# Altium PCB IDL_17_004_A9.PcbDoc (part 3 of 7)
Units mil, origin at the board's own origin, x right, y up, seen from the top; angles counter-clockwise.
Board outline 9493.25 x 7199.68 mil, 6 copper layers (Top Layer - SIG1, Layer 2 - GND1, Layer 3 - PWR1, Layer 4 - PWR2, Layer 5 - GND2, Bottom Layer - SIG2), stack 60.592 mil thick; 403 components, 274 nets, 1834 pads, 1849 vias.
Unrouted connection lines stored in the file: 1.
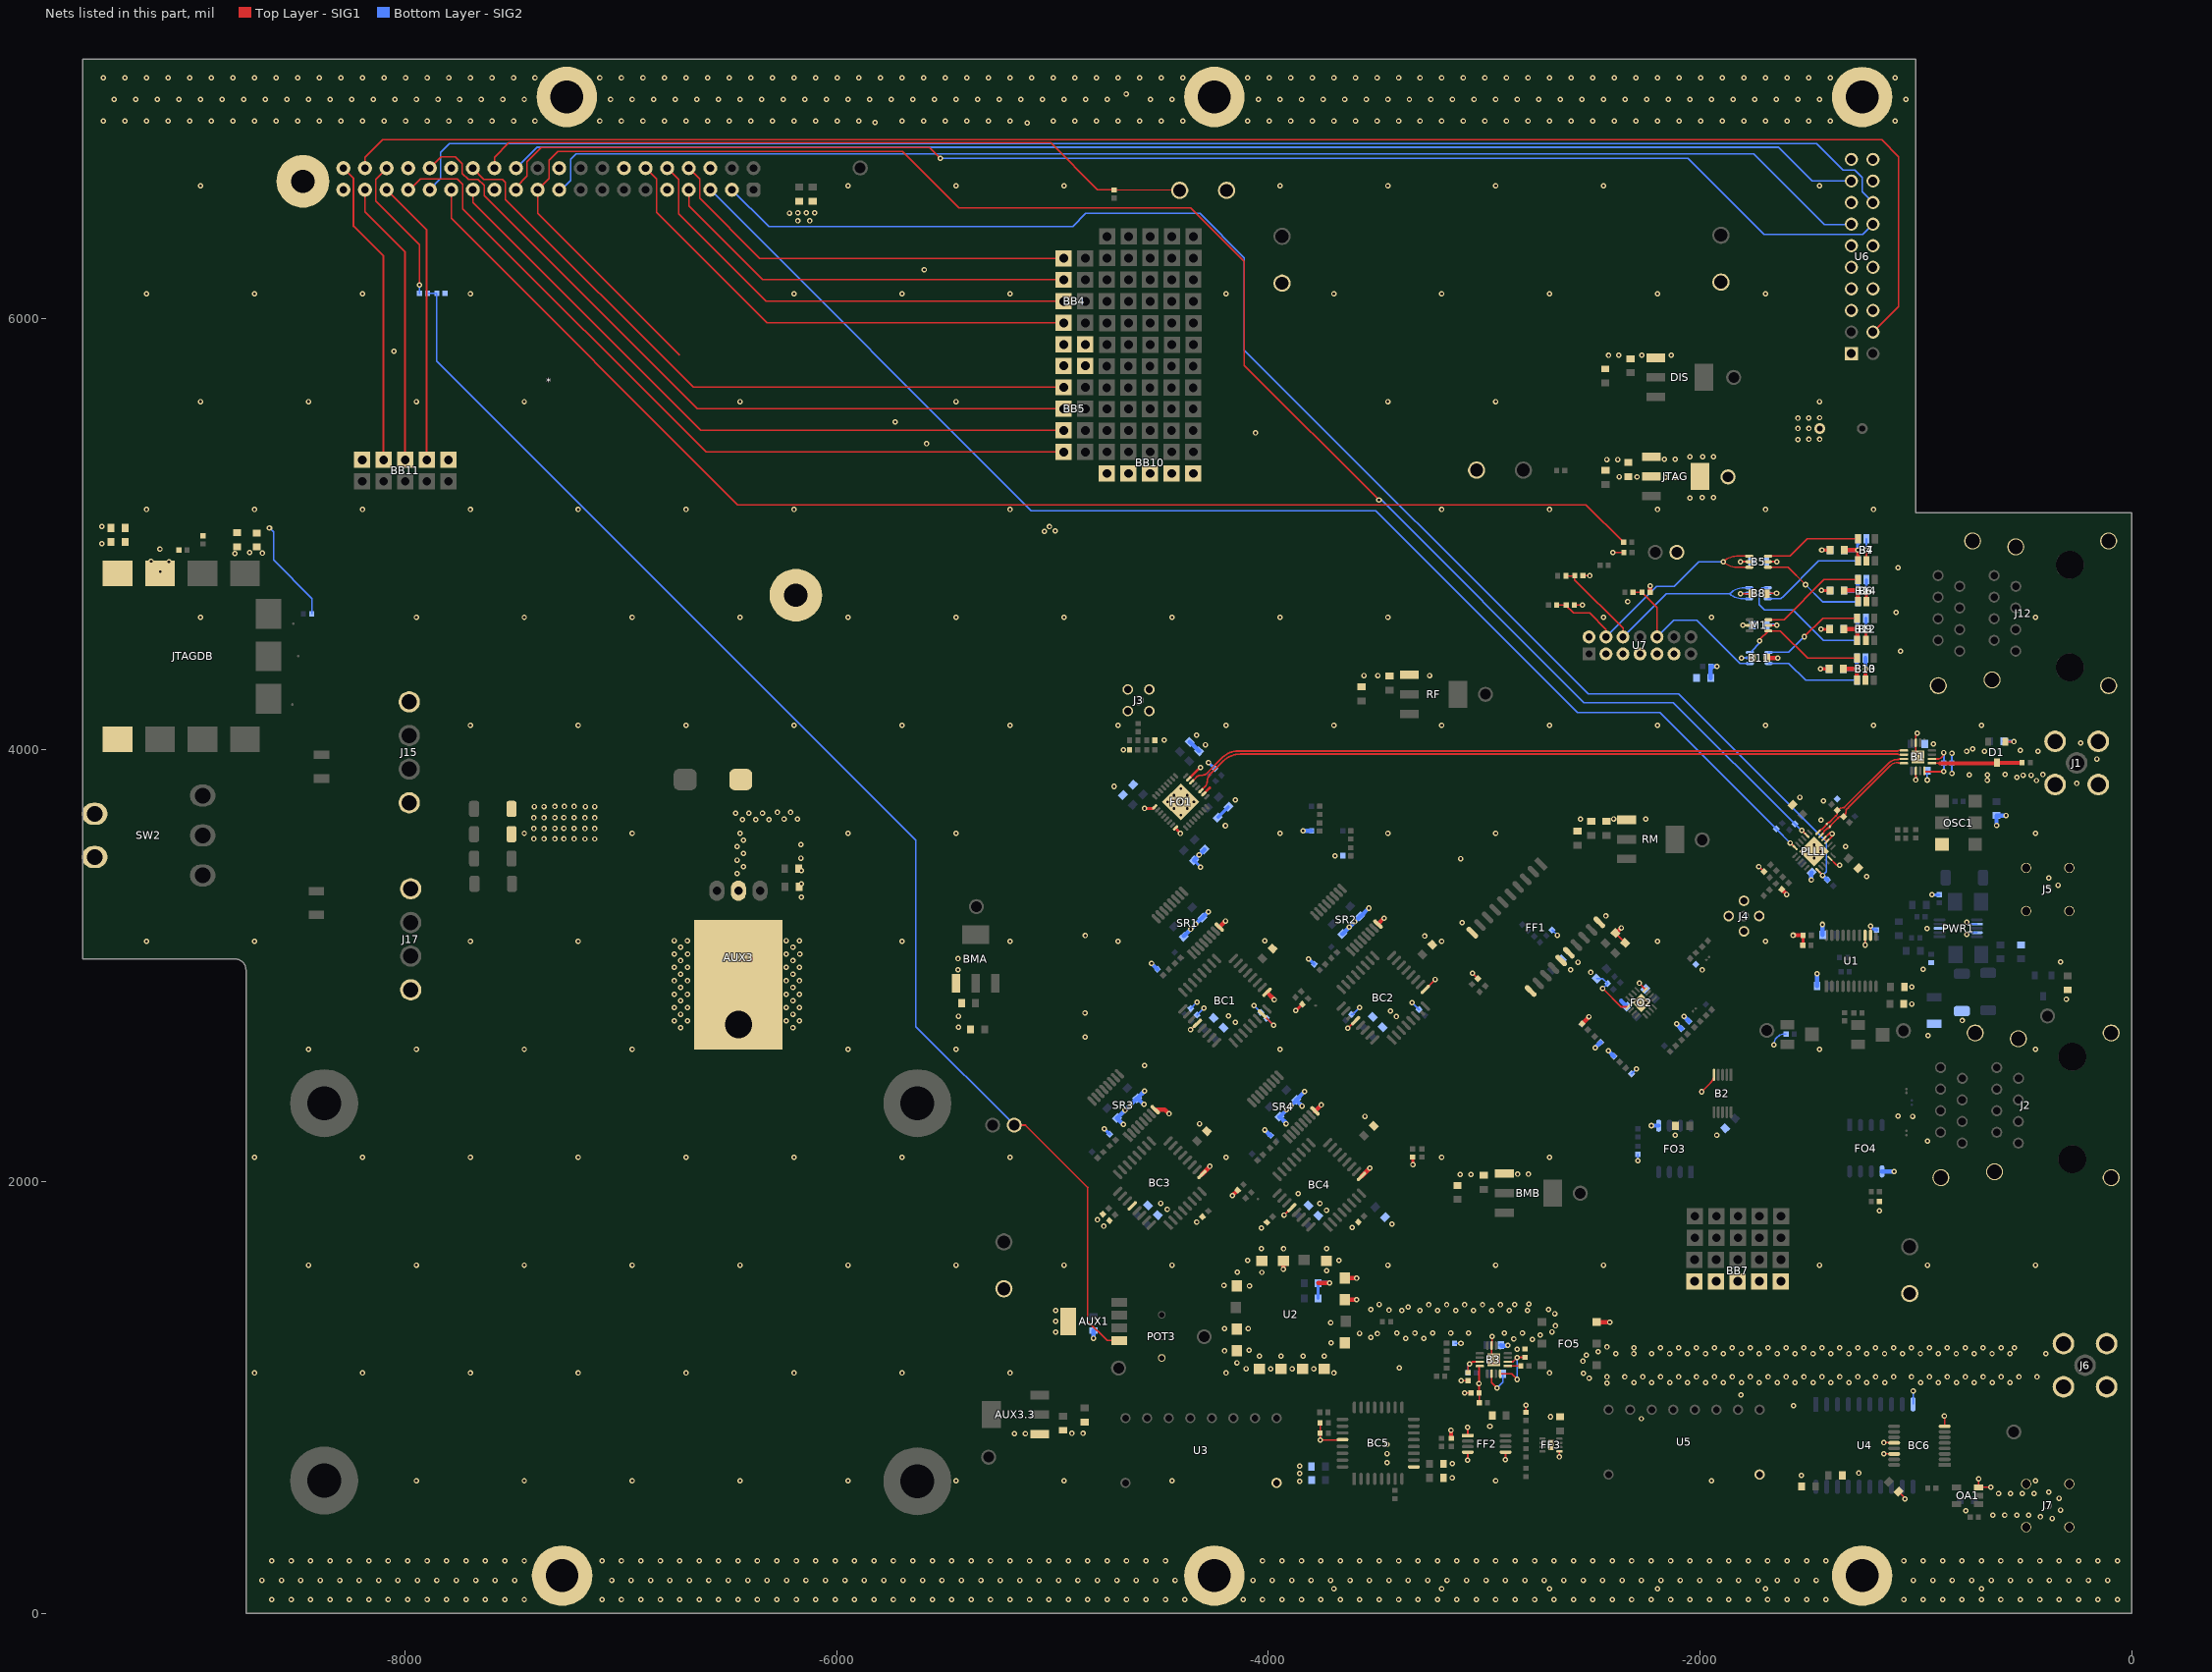
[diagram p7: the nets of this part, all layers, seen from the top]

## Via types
v1: diameter 25, hole 12, Top Layer - SIG1 to Bottom Layer - SIG2, tented both sides, 1502 vias
v2: diameter 25, hole 12, Top Layer - SIG1 to Bottom Layer - SIG2, 184 vias
v3: diameter 25.59, hole 11.81, Top Layer - SIG1 to Bottom Layer - SIG2, tented both sides, 163 vias

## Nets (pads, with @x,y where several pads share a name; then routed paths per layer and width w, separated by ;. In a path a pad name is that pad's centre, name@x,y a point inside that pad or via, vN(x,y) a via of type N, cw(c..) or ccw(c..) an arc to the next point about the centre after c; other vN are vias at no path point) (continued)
GND: *.6 *.9 *.14 *.20 *.25 *.30 *.34 *.39 *.MH2 *.MH3 AUX1.5 AUX3.2 AUX3.3.1 B1.7 B1.14 B1.17 B2.5 B3.7 B3.14 B3.17 B4.2 B5.2 B6.2 B7.2 B8.2 B9.2 B10.2 B11.2 B12.2 B13.2 B14.2 BB4.5 BB4.10 BB5.5 BB5.10 BB7.6 BB7.7 BB7.8 BB7.9 BB7.10 BB10.6 BB10.7 BB10.8 BB10.9 BB10.10 BB11.1 BB11.5 BC1.9 BC1.28 BC2.9 BC2.28 BC3.9 BC3.28 BC4.9 BC4.28 BC5.9 BC5.28 BC6.8 BC6.12 BC6.14 BMA.1 BMB.1 C1.2 C2.1 C3.2 C4.1 C5.2 C6.1 C8.2 C9.1 C11.2 C12.1 C13.2 C14.1 C15.2 C16.1 C17.2 C20.1 C26.2 C27.2 C28.1 C29.1 C32.1 C33.1 C34.2 C35.1 C36.2 C37.1 C38.2 C42.2 C43.1 C46.2 C47.1 C48.2 C49.1 C50.2 C51.1 C52.2 C53.1 C54.2 C55.2 C56.1 C59.2 C60.1 C61.2 C62.1 C63.2 C64.1 C65.2 C66.1 C67.2 C69.2 C70.1 C71.2 C72.1 C73.1 C74.2 C75.1 C76.2 C77.1 C78.2 C79.1 C80.2 C81.1 C84.1 C86.2 C87.2 C88.2 C89.2 C90.1 C91.2 C92.1 C93.2 C94.1 C95.2 C96.1 C97.2 C98.1 C99.2 C100.1 C101.2 C102.1 C103.1 C104.1 C105.1 C106.1 C107.1 C108.1 C109.1 C110.1 C111.1 C112.2 C113.1 C114.1 C115.1 C116.1 C117.2 C118.1 C119.1 C121.1 C123.1 C124.2 C400.2 C401.2 C402.1 C403.1 D1.1 D4.1 D5.2 D7.2 DIS.1 FAN3.2 FAN4.2 FF1.10 FF1.11 FF1.15 FF1.16 FF1.20 FF2.1 FF2.4 FF2.5 FF3.5 FF3.9 FO1.2 FO1.7 FO1.17 FO1.24 FO1.33 FO2.5 FO2.16 FO2.17 FO3.5 FO4.5 FO5.6 J1.2 J1.3 J1.4 J1.5 J2.17 J2.18 J2.19 J2.20 J2.21 J2.22 J3.2 J3.3 J3.4 J3.5 J4.2 J4.3 J4.4 J4.5 J5.2 J5.3 J5.4 J5.5 J6.2 J6.3 J6.4 J6.5 J7.2 J7.3 J7.4 J7.5 J9.2 J10.2 J11.2 J12.17 J12.18 J12.19 J12.20 J12.21 J12.22 J13.2 J15.1 J15.4 J17.1 J17.4 J18.2 JTAG.1 JTAGDB.1 JTAGDB.10 M1.2 MH1.1 MH2.1 MH3.1 MH4.1 MH5.1 MH6.1 OA1.3 OSC1.3 PLL1.3 PLL1.4 PLL1.23 PLL1.25 POT3.3 PWR1.3 PWR1.7 PWR1.9 R5.2 R8.1 R11.1 R12.1 R15.1 R16.1 R17.1 R18.2 R21.2 R22.1 R25.1 R27.1 R30.1 R36.2 R38.1 R40.2 R43.1 R46.2 R51.1 R52.1 R53.1 R54.1 R55.1 R56.1 R61.2 R62.2 R63.2 R64.2 R68.2 R69.2 R70.2 R71.2 R72.1 R73.1 R78.2 R79.2 R80.2 R81.2 R85.2 R86.2 R87.2 R88.2 R91.2 R92.1 R93.1 R96.1 R100.1 R101.2 R102.2 R120.1 R122.2 R123.1 RA2.2 RF.1 RM.1 SR1.8 SR2.8 SR3.8 SR4.8 SW2.4 SW2.5 U1.12 U1.13 U2.1 U2.3 U2.4 U2.5 U2.6 U2.7 U2.8 U2.9 U2.11 U2.12 U2.13 U2.15 U2.16 U3.10 U4.10 U5.10 U6.1 U6.5 U6.6 U6.7 U6.8 U6.9 U6.10 U6.11 U6.12 U6.15 U6.18 U6.19 U6.20 U7.3 U7.5 U7.7 U7.9 U7.11 | length 7139.8
  Top Layer - SIG1 w6: v1(-3927.01,1845.9) BC4.28@-3892.21,1880.03 ; R100.1@-3760.54,881.98 -3760.22,881.67 R96.1@-3760.22,836.07 -3760.33,835.97 v3(-3760.33,804.07) -3657.91,804.07 BC5.28@-3657.1,804.89 ; v1(-3631.72,2710.81) BC2.28@-3596.12,2746.41 ; v3(-3106.71,1078.21) R93.1@-3074.97,1078.21 ccw(c-3073.2,1076.44) R93.1@-3075.7,1076.44 ; R102.2@-2806.26,931.77 v1(-2806.26,965.16) ; C38.2@-2391.95,3151.33 ccw(c-2390.38,3151.34) -2391.49,3150.23 C36.2@-2347.26,3105.99 ; v1@-1727.88,3460.01 R15.1@-1704.43,3436.57 ; v3@-1359.22,3474.27 cw(c-1359.22,3471.86) v3@-1357.51,3473.57 ; v3(-1236.16,3096.68) U1.13@-1236.16,3141.85 ; U1.12@-1210.57,3141.85 v3(-1210.57,3183.56) ; v1(-1149.6,739.06) v1(-1149.6,739.06) BC6.14@-1101.6,739.11 ; v1(-1149.6,791.06) -1103.46,791.06 cw(c-1103.46,788.43) BC6.12@-1101.6,790.29 ; C79.1@-1080.73,564.34 -1050.69,534.31 v3(-1050.69,530.31) ; v1(-868.51,914.82) -867.35,913.65 BC6.8@-867.35,867.06 ; v1@-709.32,623.34 OA1.3@-709.32,584.8 v1@-653.6,584.8
  Top Layer - SIG1 w8: v1(-4361.08,2704.03) ccw(c-4361.08,2710.37) -4356.59,2705.89 -4329.26,2733.22 ccw(c-4329.26,2726.88) BC1.28@-4333.75,2731.36 ; BC5.9@-3326.39,678.9 BC5.9@-3304.45,678.9 ; BC2.9@-3273.18,2891.17 -3273.12,2891.17 v1(-3227.03,2937.26) ; v3(-3090.43,1021.34) -3090.06,1021.71 R92.1@-3061.29,1021.71 ; v3(-3077.21,710.98) ccw(c-3078.25,712.03) -3076.77,712.03 FF2.4@-3076.77,747.3 ; v3(-3077.21,861.98) cw(c-3078.25,860.93) -3076.77,860.93 FF2.1@-3076.77,824.07 ; v3(-3055.07,2966.16) -3054.99,2966.16 R70.2@-3030.28,2941.45 ; B3.14@-2965.93,1110.87 -2965.93,1070.16 v3(-2940.64,1044.87) ; v1(-2964.12,1283) -2964.12,1242.75 B3.7@-2965.96,1240.91 -2965.96,1199.67 ccw(c-2932.36,1199.67) B3.17@-2956.12,1175.91 ; v3(-2902.21,712.98) ccw(c-2903.73,714.5) -2901.58,714.5 FF2.5@-2901.58,747.3 ; v1@-2651.84,725.25 FF3.5@-2651.84,751.14 ; v1(-2600.68,2981.66) v1@-2600.68,2981.79 ; FF1.20@-2467.28,3201.95 ccw(c-2467.28,3212.67) FF1.20@-2459.71,3205.08 ; v1(-2451.23,2895.03) -2366.15,2809.95 FO2.5@-2333.41,2809.95 ; C38.2@-2391.95,3151.33 ccw(c-2391.95,3157.37) C38.2@-2387.68,3153.1 ; v1(-2281.76,2919.47) -2254.07,2891.78 FO2.16@-2254.07,2889.29 ; v3(-1993.23,2417.03) -1950.61,2459.64 ccw(c-1986.26,2495.29) B2.5@-1935.84,2495.29 ; v3(-1812.68,4872.16) B5.2@-1772.31,4872.16 ; v3(-1812.52,4723.75) C101.2@-1759.48,4723.75 ; M1.2@-1684.37,4577.53 v1@-1644.11,4577.53 ; PLL1.23@-1398.39,3497.18 -1367.77,3466.57 v3(-1354.51,3466.57) ; B4.2@-1229.37,4875.08 v1(-1229.37,4926.26) ; B1.14@-1000.84,3903.53 -1000.2,3861.06 v1@-1000.19,3860.34 ; B1.17@-1000.84,3978.93 B1.7@-1000.84,4033.53 -1000.84,4061.91 cw(c-978.33,4061.91) v1(-994.25,4077.83) ; D1.1@-586.63,4038.23 v1(-546,4038.23) ; PLL1.4@-1426.23,3590.44 PLL1.3@-1412.31,3576.52 -1389.51,3598.57 -1389,3599.08 v1(-1389,3612.42) -1391,3612.42 -1397.33,3618.75 -1401.51,3614.57 PLL1.4@-1426.23,3590.44
  Top Layer - SIG1 w12: FO1.7@-4368.92,3866.7 v1@-4316.12,3919.5 ; FO1.2@-4299.32,3797.1 -4272.08,3824.34
  Top Layer - SIG1 w13: v1(-4574.51,3729.07) -4534.39,3729.07 FO1.17@-4527.09,3736.37 ; FO1.24@-4429.65,3638.93 v1(-4408.08,3613.16)
  Top Layer - SIG1 w14: v1@-3872.35,2792.45 R69.2@-3842.71,2822.09 ; R87.2@-3331.32,2113.95 -3330.95,2113.57 v1(-3330.95,2078.57) ; R30.1@-1524.06,3096 -1524.06,3141.69 R25.1@-1523.74,3142 ; v3(-1442,4376) -1441.86,4375.86 C92.1@-1402.48,4375.86 C92.1@-1402.62,4376 ; v3(-1439.68,4560) -1439.54,4559.86 -1400.16,4559.86 C89.2@-1400.3,4560 ; v3(-1437.86,4739) -1437.72,4738.85 -1398.34,4738.85 C96.1@-1398.49,4739 ; v3(-1436.62,4926) C94.1@-1397.71,4926 ; C89.2@-1398.02,4560.14 C89.2@-1397.87,4560 ; C96.1@-1396.2,4739.14 C96.1@-1396.05,4739 ; B12.2@-1233,4507.82 v3(-1233,4559) ; B14.2@-1230,4686.82 v3(-1230,4738)
  Top Layer - SIG1 w20: SR3.8@-4524.49,2334.44 -4480.57,2334.44 v1(-4460.83,2314.7) ; BC3.9@-4308.14,2033.28 -4271.45,2069.96 v1(-4271.45,2071.48) ; SR1.8@-4227.52,3179.45 v1@-4199.08,3207.9 ; v1(-4166.51,1936.61) R86.2@-4143.26,1959.85 ; BC1.9@-4006.33,2877.98 -3984.57,2856.22 cw(c-3985.75,2855.03) -3984.08,2855.03 -3972.57,2843.53 v1(-3972.57,2843.13) ; v1(-3931.15,1594.06) U2.15@-3931.15,1633 ; SR4.8@-3784.53,2327.73 -3782.8,2327.73 v1(-3754.83,2355.7) ; -3769.33,1530.5 v1@-3716.81,1530.5 ; U2.11@-3646.15,1453 v1(-3591.15,1453) ; U2.12@-3646.15,1553 v1(-3591.57,1553) ; BC4.9@-3569.28,2024.79 v1(-3530.55,2063.51) ; SR2.8@-3492.68,3193.47 v1@-3464.7,3221.45 ; R101.2@-3153.58,811.96 v1@-3153.58,846.9 ; R53.1@-2547.58,2730.94 -2514.83,2763.69 v1(-2514.83,2764.67) ; FO5.6@-2479.15,1350 v1(-2419.12,1350) ; C38.2@-2387.68,3153.1 v1(-2364.76,3176.03) ; v3@-1996.3,2418.3 cw(c-1996.3,2413.96) v3(-1993.23,2417.03) ; R16.1@-1621.92,3354.05 v1@-1598.78,3330.91 ; v3(-1569,3142) R25.1@-1523.74,3142 ; B13.2@-1234.4,4323.63 v1(-1234.4,4374.81)
  Bottom Layer - SIG2 w6: C109.1@-4392.02,3135.26 C109.1@-4392.02,3138.21 ; v1@-3634.35,2704.45 cw(c-3625.36,2704.45) v1(-3631.72,2710.81) ; R91.2@-3136.42,1251.39 v3(-3108.12,1251.39) ; v1(-1659.25,2633.83) cw(c-1609.64,2633.83) -1609.64,2683.44 R17.1@-1601.73,2683.44 ; U4.10@-1013.79,968.71 v1(-1013.79,1030.77)
  Bottom Layer - SIG2 w8: R68.2@-4360.54,2803.01 v1@-4330.84,2832.72 ; R61.2@-4330.59,2772.12 -4298.4,2804.31 v3(-4298.4,2804.63) ; v1@-4277.55,3942.21 v1(-4277.22,3942.21) ; v1(-4066.53,2815.37) -4035.64,2784.48 R63.2@-4035.64,2784.14 ; R62.2@-3615.5,2774.94 -3610.03,2774.94 v1(-3578.43,2806.55) ; v1(-3333.93,2829.68) -3333.7,2829.68 R64.2@-3301.82,2797.8 ; v3(-2974.21,866.98) v3@-2974.06,866.83 ; v3(-2940.64,1044.87) -2913.8,1071.72 C76.2@-2913.8,1110.91 ; R27.1@-2682.86,3166.47 R27.1@-2685.86,3166.47 v1@-2661.5,3142.11 ; v1@-2504.79,2967.33 ccw(c-2503.15,2967.33) v1@-2504.31,2966.17 ; C121.1@-2478.96,2940.83 -2451.42,2940.83 R43.1@-2428.35,2917.76 -2451.08,2895.03 v1(-2451.23,2895.03) ; R52.1@-2317.86,2499.67 v1(-2295.09,2522.44) ; v1@-2289,2097 R71.2@-2289,2127.1 ; v3(-1812.68,4872.16) C91.2@-1761.48,4872.16 ; v3(-1812.52,4723.75) cw(c-1807.69,4718.92) -1807.69,4725.75 B8.2@-1772.83,4725.75 ; v1@-1809.29,4426.75 B11.2@-1769.83,4426.75 ; v1@-1389,3609.57 v1(-1389,3612.42) ; v1(-1229.37,4926.26) B7.2@-1229.37,4977.44 ; C9.1@-948.68,3903.53 -948.68,3861.68 v3(-948,3861) ; v1(-834,3891) C20.1@-834,3939 v1(-834,3985) ; v1@-766.11,3193.68 PWR1.7@-717.81,3193.68 ; v1(-765.33,3145.54) -756.55,3154.31 PWR1.9@-717.81,3154.31
  Bottom Layer - SIG2 w14: v1(-4759.93,2245.42) R72.1@-4734.87,2220.36 ; C17.2@-4345.16,3489.45 v1@-4313.59,3457.89 ; v1(-4277.22,3942.21) R8.1@-4249.21,3914.2 ; C15.2@-4234.79,3687.31 C16.1@-4185.29,3736.81 ; v1@-3812.52,3032.46 R56.1@-3787.58,3007.53 ; C69.2@-3769.33,1459.64 C114.1@-3769.33,1530.5 ; C98.1@-1692.68,4578.53 -1644.32,4578.53 v1(-1644.11,4578.73) ; v3(-1436.62,4926) cw(c-1436.62,4923.04) -1434.53,4925.13 -1399.8,4925.13 ccw(c-1399.8,4928.09) C99.2@-1397.71,4926 ; v3(-1233,4559) B9.2@-1233,4610.18 ; v3(-1230,4738) B6.2@-1230,4789.18 ; v3(-1210.57,3183.56) -1200.69,3173.68 ccw(c-1182.65,3191.71) R38.1@-1182.65,3166.2 ; v1(-926.92,3330) ccw(c-925.99,3330.93) -925.99,3329.61 R123.1@-893.25,3329.61 ; C4.1@-593.52,4040 -550.28,4040 cw(c-550.28,4033.95) v1(-546,4038.23) ; v1(-4153.54,3768.56) cw(c-4152.08,3767.1) -4152.08,3769.16 -4152.69,3768.56 v1(-4153.54,3768.56)
  Bottom Layer - SIG2 w20: v1(-4810.85,1275.22) C116.1@-4810.85,1310.9 ; v1(-4672.31,2265.14) C110.1@-4701.35,2294.18 ccw(c-4701.35,2296.59) -4699.64,2294.88 C60.1@-4607.35,2387.18 ; v1@-4579.31,2360.14 -4605.64,2386.47 ccw(c-4607.35,2384.76) C60.1@-4607.35,2387.18 ; v1(-4574.31,2420.14) C60.1@-4607.35,2387.18 ; v1@-4541.08,3010.76 R55.1@-4513.72,2983.4 ; C109.1@-4392.02,3138.21 C49.1@-4306.39,3223.84 -4305.41,3223.84 v1(-4278.83,3250.42) ; C5.2@-4363.97,4037.26 C107.1@-4321.54,3994.83 ; C17.2@-4345.16,3489.45 C6.1@-4295.66,3538.95 ; v3(-4016.55,2239.69) -3991.28,2214.41 R73.1@-3989.79,2214.41 ; v1@-3918.61,2270.68 ccw(c-3916.91,2272.38) -3916.91,2269.97 -3947.23,2300.3 ccw(c-3948.94,2298.59) C62.1@-3948.94,2301 -3947.41,2301 C67.2@-3870.41,2378 ; C67.2@-3870.82,2378 ccw(c-3872.53,2379.71) C67.2@-3870.12,2379.71 ; v1(-3844.08,2350.68) -3869.7,2376.3 cw(c-3868,2378) C67.2@-3870.41,2378 ; v1(-3838.51,3625.09) R18.2@-3800.03,3625.09 ; v1@-3831.15,2418.68 C67.2@-3870.12,2379.71 ; C114.1@-3769.33,1530.5 -3719.22,1530.5 ccw(c-3719.22,1533.92) v1(-3716.81,1531.5) ; C42.2@-3656.79,3148.27 C43.1@-3576.08,3228.98 -3573.82,3228.98 v3(-3535.35,3267.45) ; v1(-3591.57,1553) ccw(c-3591.57,1556.41) v1@-3589.15,1554 ; v1@-3531.55,2062.69 -3530.73,2063.51 v1(-3530.55,2063.51) ; C75.1@-2923.01,1243.57 -2920.18,1240.74 -2893.22,1240.74 v3(-2891.12,1242.83) ; v1@-2486.28,2621.07 R54.1@-2461.89,2645.47 ; v1@-2423.93,2605.95 R51.1@-2399.52,2581.55 ; -2365.39,2837.75 C26.2@-2338.63,2810.99 ; v3(-2225.77,2260) -2225.48,2259.71 FO3.5@-2192.5,2259.71 ; v3(-2109.5,2732.08) -2109.5,2731.74 R46.2@-2086.83,2709.07 ; v1(-2075.5,2766.08) cw(c-2075.5,2764.28) -2074.23,2765.55 R40.2@-2051.98,2743.3 cw(c-2051.98,2745.1) R40.2@-2053.25,2743.83 ; v1(-1484.9,3398.57) -1484.9,3430.15 C14.1@-1482.6,3432.46 ; v3(-1459,2963) -1458.62,2962.62 C37.1@-1458.62,2906.74 ; v3(-1433,3192) -1432.62,3191.62 C35.1@-1432.62,3143.74 ; v1(-1234.4,4374.81) B10.2@-1234.4,4425.99 ; FO4.5@-1157.72,2047.84 -1102.76,2047.84 cw(c-1102.76,2046.36) v3(-1101.72,2047.4) ; v1(-627.25,3650.83) -627.54,3651.12 C3.2@-627.54,3696.72 -582.36,3696.72 v1(-582.25,3696.83) ; C60.1@-4607.35,2387.18 cw(c-4607.35,2384.76) C60.1@-4607.35,2387.18 ; C60.1@-4607.35,2387.18 C60.1@-4607.35,2387.18 ; C67.2@-3870.41,2378 -3868.72,2376.31 cw(c-3865.29,2379.71) C67.2@-3870.12,2379.71
  other v1: -8617,63.9 -8527,63.9 -8437,63.9 -8347,63.9 -8257,63.9 -8167,63.9 -8077,63.9 -7987,63.9 -7897,63.9 -7807,63.9 -7717,63.9 -7627,63.9 -7537,63.9 -7447,63.9 -7087,63.9 -6997,63.9 -6907,63.9 -6817,63.9 -6727,63.9 -6637,63.9 -6547,63.9 -6457,63.9 -6367,63.9 -6277,63.9 -6187,63.9 -6097,63.9 -6007,63.9 -5917,63.9 -5827,63.9 -5737,63.9 -5647,63.9 -5557,63.9 -5467,63.9 -5377,63.9 -5287,63.9 -5197,63.9 -5107,63.9 -5017,63.9 -4927,63.9 -4837,63.9 -4747,63.9 -4657,63.9 -4567,63.9 -4477,63.9 -4387,63.9 -4117,63.9 -4027,63.9 -3937,63.9 -3847,63.9 -3757,63.9 -3667,63.9 -3577,63.9 -3487,63.9 -3397,63.9 -3307,63.9 -3217,63.9 -3127,63.9 -3037,63.9 -2947,63.9 -2857,63.9 -2767,63.9 -2677,63.9 -2587,63.9 -2497,63.9 -2407,63.9 -2317,63.9 -2227,63.9 -2137,63.9 -2047,63.9 -1957,63.9 -1867,63.9 -1777,63.9 -1687,63.9 -1597,63.9 -1507,63.9 -1417,63.9 -1057,63.9 -967,63.9 -877,63.9 -787,63.9 -697,63.9 -607,63.9 -517,63.9 -427,63.9 -337,63.9 -247,63.9 -157,63.9 -67,63.9 -3697,113.9 -3197,113.9 -2697,113.9 -2197,113.9 -1697,113.9 -697,113.9 -8662,153.9 -8572,153.9 -8482,153.9 -8392,153.9 -8302,153.9 -8212,153.9 -8122,153.9 -8032,153.9 -7942,153.9 -7852,153.9 -7762,153.9 -7672,153.9 -7582,153.9 -7492,153.9 -7042,153.9 -6952,153.9 -6862,153.9 -6772,153.9 -6682,153.9 -6592,153.9 -6502,153.9 -6412,153.9 -6322,153.9 -6232,153.9 -6142,153.9 -6052,153.9 -5962,153.9 -5872,153.9 -5782,153.9 -5692,153.9 -5602,153.9 -5512,153.9 -5422,153.9 -5332,153.9 -5242,153.9 -5152,153.9 -5062,153.9 -4972,153.9 -4882,153.9 -4792,153.9 -4702,153.9 -4612,153.9 -4522,153.9 -4432,153.9 -4072,153.9 -3982,153.9 -3892,153.9 -3802,153.9 -3712,153.9 -3622,153.9 -3532,153.9 -3442,153.9 -3352,153.9 -3262,153.9 -3172,153.9 -3082,153.9 -2992,153.9 -2902,153.9 -2812,153.9 -2722,153.9 -2632,153.9 -2542,153.9 -2452,153.9 -2362,153.9 -2272,153.9 -2182,153.9 -2092,153.9 -2002,153.9 -1912,153.9 -1822,153.9 -1732,153.9 -1642,153.9 -1552,153.9 -1462,153.9 -1012,153.9 -922,153.9 -832,153.9 -742,153.9 -652,153.9 -562,153.9 -472,153.9 -382,153.9 -292,153.9 -202,153.9 -112,153.9 -8617,243.9 -8527,243.9 -8437,243.9 -8347,243.9 -8257,243.9 -8167,243.9 -8077,243.9 -7987,243.9 -7897,243.9 -7807,243.9 -7717,243.9 -7627,243.9 -7537,243.9 -7447,243.9 -7087,243.9 -6997,243.9 -6907,243.9 -6817,243.9 -6727,243.9 -6637,243.9 -6547,243.9 -6457,243.9 -6367,243.9 -6277,243.9 -6187,243.9 -6097,243.9 -6007,243.9 -5917,243.9 -5827,243.9 -5737,243.9 -5647,243.9 -5557,243.9 -5467,243.9 -5377,243.9 -5287,243.9 -5197,243.9 -5107,243.9 -5017,243.9 -4927,243.9 -4837,243.9 -4747,243.9 -4657,243.9 -4567,243.9 -4477,243.9 -4027,243.9 -3937,243.9 -3847,243.9 -3757,243.9 -3667,243.9 -3577,243.9 -3487,243.9 -3397,243.9 -3307,243.9 -3217,243.9 -3127,243.9 -3037,243.9 -2947,243.9 -2857,243.9 -2767,243.9 -2677,243.9 -2587,243.9 -2497,243.9 -2407,243.9 -2317,243.9 -2227,243.9 -2137,243.9 -2047,243.9 -1957,243.9 -1867,243.9 -1777,243.9 -1687,243.9 -1597,243.9 -1507,243.9 -1417,243.9 -1057,243.9 -967,243.9 -877,243.9 -787,243.9 -697,243.9 -607,243.9 -517,243.9 -427,243.9 -337,243.9 -247,243.9 -157,243.9 -67,243.9 -653.23,584.43 -3855.39,613 -7947,613.9 -7447,613.9 -6947,613.9 -6447,613.9 -5947,613.9 -5447,613.9 -4947,613.9 -4447,613.9 -2947,613.9 -1947,613.9 -447,613.9 -709.23,623.43 -3148.97,627.92 -1530.84,640.16 -3854.94,648.03 -1264.84,650.16 -3855.16,683.06 -3450.8,698.47 -2652.07,725.02 -3449.81,740.79 -2691.21,780.66 -3449.81,782.13 -5176.04,832.35 -5125.35,832.35 -4909.8,834.32 -4859.11,834.32 -3153.84,848.16 -2272.87,902.35 -1568,962 -1811,1013 -8697,1113.9 -8197,1113.9 -7697,1113.9 -7197,1113.9 -6697,1113.9 -6197,1113.9 -5697,1113.9 -5197,1113.9 -4197,1113.9 -3697,1113.9 -2697,1113.9 -3890.34,1132.9 -3790.14,1132.54 -4102.33,1134.08 -3990.18,1133.97 -3393.41,1136.96 -4145.29,1161.32 -3942.12,1192 -4041.12,1193 -3840.12,1193 -3741.12,1193 -4202.39,1216.33 -4089.12,1219 -2848.67,1223.87 -3709.12,1253 -4984.6,1303.06 -4202.92,1319.02 -4093.12,1319 -4985.6,1353.06 -4985.6,1404.06 -4088.12,1518 -4206.31,1520.45 -4031.12,1580 -4143.71,1580.46 -3730.84,1588.16 -8447,1613.9 -7947,1613.9 -7447,1613.9 -6947,1613.9 -6447,1613.9 -5947,1613.9 -5447,1613.9 -4947,1613.9 -4447,1613.9 -3447,1613.9 -2947,1613.9 -2447,1613.9 -1447,1613.9 -947,1613.9 -447,1613.9 -4096.56,1634.94 -3673.76,1636.52 -4032.64,1689.96 -3929.43,1689.43 -3730.34,1689.96 -4762.32,1793.76 -4331.68,1812.6 -4791.82,1823.43 -1169.45,1865.28 -3731,1867.85 -4468.1,1872.66 -3761.17,1900.31 -4498.72,1900.5 -3862.14,1944.64 -3112.34,2032.94 -3061.65,2032.94 -2846.1,2034.9 -2795.41,2034.9 -2288,2097 -8697,2113.9 -8197,2113.9 -7697,2113.9 -7197,2113.9 -6697,2113.9 -6197,2113.9 -5697,2113.9 -5197,2113.9 -4197,2113.9 -3197,2113.9 -2697,2113.9 -946,2188 -2115,2215 -1923.25,2215.83 -4319.25,2268.77 -3917.91,2268.97 -3552.55,2302.95 -1016,2303 -1084,2304 -4663.83,2330.7 -3916.76,2333.3 -3895.71,2352.7 -4639.83,2354.7 -4575.31,2358.14 -3832.08,2417.68 -4573.96,2538.38 -2424.71,2605.95 -8447,2613.9 -7947,2613.9 -7447,2613.9 -6947,2613.9 -5947,2613.9 -5447,2613.9 -3947,2613.9 -1447,2613.9 -447,2613.9 -2486.28,2620.62 -4849,2671 -945.25,2677.83 -6722,2714 -6203,2714 -5436.09,2716.22 -4153.19,2738.22 -6753,2745 -6691,2745 -6234,2745 -6172,2745 -786.25,2746.83 -3406.83,2764.95 -5436.09,2766.91 -4184.19,2768.22 -6722,2776 -6203,2776 -4850,2782 -3434.86,2791.49 -3873.35,2792.45 -6753,2807 -6691,2807 -6234,2807 -6172,2807 -1020.25,2823.68 -2295.69,2829.88 -2251.4,2829.88 -4329.89,2831.2 -6722,2838 -6203,2838 -304.25,2845.83 -6753,2869 -6692,2869 -6234,2869 -6173,2869 -6722,2900 -6203,2900 -1020.25,2902.43 -6753,2931 -6691,2931 -6234,2931 -6172,2931 -6722,2962 -6203,2962 -2506.91,2969.45 -1991.23,2981.03 -5438.06,2982.46 -967,2985 -6753,2993 -6691,2993 -6234,2993 -6172,2993 -4541.08,3011.03 -2565.32,3017.15 -330.25,3017.83 -6722,3024 -6203,3024 -3813.61,3031.48 -5438.06,3033.15 -6753,3055 -6690,3055 -6234,3055 -6171,3055 -6722,3086 -6203,3086 -9197,3113.9 -8697,3113.9 -7697,3113.9 -7197,3113.9 -5697,3113.9 -5197,3113.9 -4697,3113.9 -3197,3113.9 -2197,3113.9 -1697,3113.9 -6692,3116 -6173,3116 -4017.25,3115.77 -6753,3117 -6234,3117 -3276.25,3137.77 -4848,3140 -2661.23,3142.11 -4360.53,3169.71 -949,3173 -3625.35,3179.72 -4337.89,3192.35 -3102.02,3200.16 -765.33,3201.64 -3600.61,3204.45 -4199.08,3208.03 -3463.35,3221.45 -2437.23,3231.03 -6163,3318 -1599,3330.91 -6163,3380 -1229,3414 -6462,3428 -6163,3442 -4314.3,3457.18 -6431,3459 -1728.08,3460.01 -6462,3490 -3108.55,3496.92 -6166,3499 -3691.13,3510.09 -4320.57,3514.04 -6431,3521 -6462,3552 -1326,3553 -6166,3561 -6431,3583 -7401.91,3588.05 -7355.91,3588.05 -7305.91,3588.16 -7262.91,3588.16 -7216.91,3588.16 -7166.28,3587.93 -7120.28,3587.93 -7447,3613.9 -6947,3613.9 -6447,3613.9 -5947,3613.9 -5447,3613.9 -3947,3613.9 -3447,3613.9 -2947,3613.9 -447,3613.9 -7401.91,3635.93 -7355.91,3635.93 -7305.91,3636.05 -7262.91,3636.05 -7216.91,3636.05 -7166.28,3635.81 -7120.28,3635.81 -1441,3675 -6437,3677 -6375,3677 -6313,3677 -2554.67,3679.22 -2251.52,3679.22 -6244,3680 -6182,3680 -2401,3681 -7401.91,3685.93 -7355.91,3685.93 -7305.91,3686.05 -7262.91,3686.05 -7216.91,3686.05 -7166.28,3685.81 -7120.28,3685.81 -6468,3708 -6406,3708 -6344,3708 -6275,3711 -6213,3711 -7399.91,3737.93 -7355.91,3737.93 -7305.91,3738.05 -7260.91,3738.05 -7216.91,3738.05 -7164.28,3737.81 -7120.28,3737.81 -1429.51,3763.57 -1538,3781 -1000.9,3861.05 -4314.67,3918.04 -4671.89,4001.47 -4292.56,4024.48 -920.25,4027.83 -4483.63,4045.36 -4333.56,4068.48 -7697,4113.9 -7197,4113.9 -6697,4113.9 -6197,4113.9 -5697,4113.9 -5197,4113.9 -4697,4113.9 -4197,4113.9 -3697,4113.9 -3197,4113.9 -2697,4113.9 -2197,4113.9 -1697,4113.9 -1197,4113.9 -697,4113.9 -3556.68,4344.88 -3492.7,4344.88 -3253.53,4344.88 -1809.29,4426.4 -1072.58,4458.37 -8947,4613.9 -7947,4613.9 -7447,4613.9 -6947,4613.9 -6447,4613.9 -5947,4613.9 -5447,4613.9 -4947,4613.9 -4447,4613.9 -3947,4613.9 -3447,4613.9 -2447,4613.9 -1947,4613.9 -447,4613.9 -1092.17,4637.09 -2335.3,4687.74 -9133.36,4826.21 -1083,4845 -9093.36,4872.21 -9175.36,4873.21 -8787.78,4910.7 -8660.78,4911.7 -8718.78,4914.7 -9134.36,4931.21 -9403.18,4956.14 -9403.18,5035.29 -9197,5113.9 -8697,5113.9 -8197,5113.9 -7697,5113.9 -7197,5113.9 -6697,5113.9 -6197,5113.9 -5197,5113.9 -3197,5113.9 -2697,5113.9 -2197,5113.9 -1697,5113.9 -1197,5113.9 -2432.67,5345.68 -2381.98,5345.68 -2166.43,5347.65 -2115.74,5347.65 -5582.7,5418.69 -1547,5438 -1496,5439 -1446,5439 -4060.28,5468.63 -1547,5489 -1496,5489 -5729.69,5519.19 -1547,5537 -1496.5,5538 -1446,5539 -8947,5613.9 -8447,5613.9 -7947,5613.9 -7447,5613.9 -6447,5613.9 -5447,5613.9 -3447,5613.9 -2947,5613.9 -1447,5613.9 -2423.93,5827.94 -2376.93,5828.94 -2269.93,5828.94 -2133.93,5828.94 -8051.19,5847.03 -9197,6113.9 -8697,6113.9 -8197,6113.9 -7697,6113.9 -6197,6113.9 -5697,6113.9 -5197,6113.9 -4197,6113.9 -3697,6113.9 -3197,6113.9 -2697,6113.9 -2197,6113.9 -1697,6113.9 -5593.89,6225.01 -6180.36,6451.02 -6124.36,6451.02 -6218.87,6487.09 -6180.36,6488.02 -6140.18,6488.68 -6101.18,6488.68 -8947,6613.9 -5947,6613.9 -5447,6613.9 -4947,6613.9 -3947,6613.9 -3447,6613.9 -2947,6613.9 -2447,6613.9 -1447,6613.9 -5118,6905 -5823,6907 -9397,6913.9 -9297,6913.9 -9197,6913.9 -9097,6913.9 -8997,6913.9 -8897,6913.9 -8797,6913.9 -8697,6913.9 -8597,6913.9 -8497,6913.9 -8397,6913.9 -8297,6913.9 -8197,6913.9 -8097,6913.9 -7997,6913.9 -7897,6913.9 -7797,6913.9 -7697,6913.9 -7597,6913.9 -7497,6913.9 -7397,6913.9 -7097,6913.9 -6997,6913.9 -6897,6913.9 -6797,6913.9 -6697,6913.9 -6597,6913.9 -6497,6913.9 -6397,6913.9 -6297,6913.9 -6197,6913.9 -6097,6913.9 -5997,6913.9 -5897,6913.9 -5697,6913.9 -5597,6913.9 -5497,6913.9 -5397,6913.9 -5297,6913.9 -5197,6913.9 -4997,6913.9 -4897,6913.9 -4797,6913.9 -4697,6913.9 -4597,6913.9 -4497,6913.9 -4397,6913.9 -4097,6913.9 -3997,6913.9 -3897,6913.9 -3797,6913.9 -3697,6913.9 -3597,6913.9 -3497,6913.9 -3397,6913.9 -3297,6913.9 -3197,6913.9 -3097,6913.9 -2997,6913.9 -2897,6913.9 -2797,6913.9 -2697,6913.9 -2597,6913.9 -2497,6913.9 -2397,6913.9 -2297,6913.9 -2197,6913.9 -2097,6913.9 -1997,6913.9 -1897,6913.9 -1797,6913.9 -1697,6913.9 -1597,6913.9 -1497,6913.9 -1397,6913.9 -1097,6913.9 -9347,7013.9 -9247,7013.9 -9147,7013.9 -9047,7013.9 -8947,7013.9 -8847,7013.9 -8747,7013.9 -8647,7013.9 -8547,7013.9 -8447,7013.9 -8347,7013.9 -8247,7013.9 -8147,7013.9 -8047,7013.9 -7947,7013.9 -7847,7013.9 -7747,7013.9 -7647,7013.9 -7547,7013.9 -7447,7013.9 -7047,7013.9 -6947,7013.9 -6847,7013.9 -6747,7013.9 -6647,7013.9 -6547,7013.9 -6447,7013.9 -6347,7013.9 -6247,7013.9 -6147,7013.9 -6047,7013.9 -5947,7013.9 -5847,7013.9 -5747,7013.9 -5647,7013.9 -5547,7013.9 -5447,7013.9 -5347,7013.9 -5247,7013.9 -5147,7013.9 -5047,7013.9 -4947,7013.9 -4847,7013.9 -4747,7013.9 -4547,7013.9 -4447,7013.9 -4047,7013.9 -3947,7013.9 -3847,7013.9 -3747,7013.9 -3647,7013.9 -3547,7013.9 -3447,7013.9 -3347,7013.9 -3247,7013.9 -3147,7013.9 -3047,7013.9 -2947,7013.9 -2847,7013.9 -2747,7013.9 -2647,7013.9 -2547,7013.9 -2447,7013.9 -2347,7013.9 -2247,7013.9 -2147,7013.9 -2047,7013.9 -1947,7013.9 -1847,7013.9 -1747,7013.9 -1647,7013.9 -1547,7013.9 -1447,7013.9 -1047,7013.9 -4659,7039 -9397,7113.9 -9297,7113.9 -9197,7113.9 -9097,7113.9 -8997,7113.9 -8897,7113.9 -8797,7113.9 -8697,7113.9 -8597,7113.9 -8497,7113.9 -8397,7113.9 -8297,7113.9 -8197,7113.9 -8097,7113.9 -7997,7113.9 -7897,7113.9 -7797,7113.9 -7697,7113.9 -7597,7113.9 -7497,7113.9 -7397,7113.9 -7097,7113.9 -6997,7113.9 -6897,7113.9 -6797,7113.9 -6697,7113.9 -6597,7113.9 -6497,7113.9 -6397,7113.9 -6297,7113.9 -6197,7113.9 -6097,7113.9 -5997,7113.9 -5897,7113.9 -5797,7113.9 -5697,7113.9 -5597,7113.9 -5497,7113.9 -5397,7113.9 -5297,7113.9 -5197,7113.9 -5097,7113.9 -4997,7113.9 -4897,7113.9 -4797,7113.9 -4697,7113.9 -4597,7113.9 -4497,7113.9 -4397,7113.9 -4097,7113.9 -3997,7113.9 -3897,7113.9 -3797,7113.9 -3697,7113.9 -3597,7113.9 -3497,7113.9 -3397,7113.9 -3297,7113.9 -3197,7113.9 -3097,7113.9 -2997,7113.9 -2897,7113.9 -2797,7113.9 -2697,7113.9 -2597,7113.9 -2497,7113.9 -2397,7113.9 -2297,7113.9 -2197,7113.9 -2097,7113.9 -1997,7113.9 -1897,7113.9 -1797,7113.9 -1697,7113.9 -1597,7113.9 -1497,7113.9 -1397,7113.9 -1097,7113.9
  other v2: -369.87,440.6 -424.4,447.76 -643.73,456.31 -588.73,456.31 -533.73,456.31 -478.73,456.31 -770.11,475.72 -330.73,479.24 -337.38,533.84 -617.92,555.81 -562.92,555.81 -507.92,555.81 -452.92,555.81 -384.44,562.3 -2430.92,1067.11 -2307.33,1069.72 -2224.33,1069.72 -2141.33,1069.72 -2058.33,1069.72 -1975.33,1069.72 -1892.33,1069.72 -1809.33,1069.72 -1726.33,1069.72 -1643.33,1069.72 -1560.33,1069.72 -1477.33,1069.72 -1394.33,1069.72 -1311.33,1069.72 -1228.33,1069.72 -1145.33,1069.72 -979.33,1069.72 -896.33,1069.72 -813.33,1069.72 -730.33,1069.72 -647.33,1069.72 -564.33,1069.72 -2514.67,1090.67 -2431.83,1095.94 -2348.83,1095.94 -2265.83,1095.94 -2182.83,1095.94 -2099.83,1095.94 -2016.83,1095.94 -1933.83,1095.94 -1850.83,1095.94 -1767.83,1095.94 -1684.83,1095.94 -1601.83,1095.94 -1518.83,1095.94 -1435.83,1095.94 -1352.83,1095.94 -1269.83,1095.94 -1186.83,1095.94 -1103.83,1095.94 -1020.83,1095.94 -937.83,1095.94 -854.83,1095.94 -771.83,1095.94 -688.83,1095.94 -605.83,1095.94 -522.83,1095.94 -439.83,1095.94 -2540.6,1111.91 -2543.63,1168.46 -2527.74,1197.06 -2390.78,1204.06 -2307.78,1204.06 -2224.78,1204.06 -2141.78,1204.06 -2058.78,1204.06 -1975.78,1204.06 -1892.78,1204.06 -1809.78,1204.06 -1726.78,1204.06 -1643.78,1204.06 -1560.78,1204.06 -1477.78,1204.06 -1394.78,1204.06 -1311.78,1204.06 -1228.78,1204.06 -1145.78,1204.06 -1062.78,1204.06 -979.78,1204.06 -896.78,1204.06 -813.78,1204.06 -730.78,1204.06 -647.78,1204.06 -564.78,1204.06 -398.78,1204.06 -2473.34,1212.6 -2307.1,1230.28 -2183.28,1230.28 -2100.28,1230.28 -2017.28,1230.28 -1934.28,1230.28 -1851.28,1230.28 -1768.28,1230.28 -1685.28,1230.28 -1602.28,1230.28 -1519.28,1230.28 -1436.28,1230.28 -1353.28,1230.28 -1270.28,1230.28 -1187.28,1230.28 -1104.28,1230.28 -1021.28,1230.28 -938.28,1230.28 -855.28,1230.28 -772.28,1230.28 -689.28,1230.28 -606.28,1230.28 -544.03,1230.28 -2430.95,1234.46 -2776.71,1270.25 -2862.95,1271.88 -3363.37,1273.51 -3280.37,1273.51 -3524.96,1278.04 -2741.52,1289.42 -3494.93,1295.84 -3577.91,1297.92 -3404.87,1299.74 -3321.87,1299.74 -3238.87,1299.74 -3155.87,1299.74 -3072.87,1299.74 -2906.87,1299.74 -2823.87,1299.74 -2687.12,1304.74 -2670.54,1332.44 -3711.04,1347.09 -2673.81,1388.8 -3381.68,1403.82 -3298.68,1403.82 -3215.68,1403.82 -3132.68,1403.82 -3049.68,1403.82 -2966.68,1403.82 -2883.68,1403.82 -2800.68,1403.82 -3441.83,1405.06 -3524.77,1408.08 -2702.31,1409.12 -3352.98,1419.79 -3257.18,1430.05 -3174.18,1430.05 -3091.18,1430.05 -3008.18,1430.05 -2925.18,1430.05 -2859.44,1431.36 -3486.9,1432.13 -2793.7,1432.68 -341.29,3373.98 -385.75,3406.36 -1472.86,3499.27 -1503.48,3529.89 -1442.23,3529.89 -1472.86,3560.51 -4406.25,3698.53 -4436.87,3729.15 -4375.63,3729.15 -4467.49,3759.77 -4406.25,3759.77 -4345,3759.77 -4436.87,3790.4 -4375.63,3790.4 -4406.25,3821.02 -255.56,3845.07 -670.34,3859.33 -442.48,3858.52 -532.84,3873.17 -504.26,3883.33 -467.07,3883.33 -753.2,3884.94 -670.2,3884.94 -587.21,3886.17 -412.13,3885.94 -162.74,3958.53 -765.72,3993.06 -682.72,3993.06 -435.32,3994.06 -517.79,3998.29 -737.46,4004.66 -237.09,4033.21
  other v3: -3148.06,693.91 -2693.06,911.47 -4032.85,1785.83 -3611.48,1788.28 -3427.39,1804.57 -4199.51,3649.34 -4714.27,3831.43
JTAG_3V3: B4.1 B5.5 B6.1 B7.1 B8.5 B9.1 B10.1 B11.5 B12.1 B13.1 B14.1 C89.1 C90.2 C91.1 C92.2 C93.1 C94.2 C95.1 C96.2 C97.1 C98.2 C99.1 C100.2 C101.1 C119.2 C400.1 C401.1 C402.2 C403.2 JTAG.2 JTAG.4 JTAGDB.11 M1.5 R109.2 R110.2 R111.2 R112.2 R117.2 RA1.2 RA3.2 TP24.1 U7.2 | length 2005
  Top Layer - SIG1 w6: R110.2@-2583.1,4672 v1@-2546,4672 ; R111.2@-2542.94,4807 v1(-2511,4807) ; v3(-2403.84,4915.31) R117.2@-2353.74,4915.31 ; v3@-1810.68,4577.53 v3@-1801.5,4577.53 ; v3(-1801.71,4577.98) -1801.5,4577.76 v3@-1801.5,4577.53 ; M1.5@-1770.98,4577.53 v3@-1801.5,4577.53
  Top Layer - SIG1 w8: C101.1@-1694.52,4723.75 cw(c-1687.03,4716.26) -1687.03,4726.85 -1685.93,4725.75 v3(-1645.97,4725.75) ; B5.5@-1685.69,4872.16 v3(-1645,4872.16)
  Top Layer - SIG1 w20: v3(-2231.5,4759.49) -2231.6,4759.39 R112.2@-2231.6,4730.14 R112.2@-2231.09,4729.63 ; C97.1@-1691.52,4426.75 -1641.33,4426.75 v1(-1640.98,4426.4) ; C92.2@-1337.52,4375.86 -1275.54,4375.86 -1274.54,4376.86 v3(-1273.77,4376.09) B13.1@-1273.77,4323.63 ; C89.1@-1335.34,4560 -1273,4560 v3(-1272,4559) B12.1@-1272,4508.19 ; C96.2@-1333.52,4739 -1270.75,4739 -1269.75,4738 v3@-1269.37,4737.63 ; C94.2@-1332.75,4926 -1269.11,4926 v3(-1268.62,4925.51) B4.1@-1268.62,4875.19 ; B14.1@-1269.37,4686.82 v3@-1269.37,4737.63 ; v3(-1269,4738) v3@-1269.37,4737.63
  Bottom Layer - SIG2 w6: v3(-8627.46,5029.15) -8609,5010.68 -8609,4880.01 -8431.12,4702.14 RA3.2@-8431.12,4629.53 ; v3(-1801.71,4577.98) -1801.16,4578.53 C98.2@-1757.64,4578.53 cw(c-1760.05,4580.94) C98.2@-1760.05,4577.53 ; v3(-1273.77,4376.09) cw(c-1265.68,4376.09) v3@-1271.4,4381.81
  Bottom Layer - SIG2 w8: C91.1@-1696.52,4872.16 v3(-1645,4872.16) ; B8.5@-1686.21,4725.75 v3(-1645.97,4725.75) ; B11.5@-1683.21,4426.75 v1@-1640,4426.75
  Bottom Layer - SIG2 w20: C93.1@-1951.01,4333.53 -1951.01,4387.25 R109.2@-1950.42,4387.84 v1@-1922.72,4387.84 ; C119.2@-1337.52,4375.86 -1337.29,4376.09 v3(-1273.77,4376.09) B10.1@-1273.77,4425.99 ; C100.2@-1335.52,4560 -1334.52,4559 v3(-1272,4559) -1272.37,4559.37 B9.1@-1272.37,4610.18 ; C99.1@-1332.75,4926 -1269.11,4926 v3@-1268.74,4925.63 ; C95.1@-1332.52,4738 v3(-1269,4738) -1269,4788.81 B6.1@-1269.37,4789.18 ; B7.1@-1268.74,4977.44 v3@-1268.74,4926 ; v3@-1268.74,4925.63 v3(-1268.62,4925.51) -1268.62,4926 v3@-1268.74,4926 ; v3@-1268.74,4925.63 v3@-1268.74,4926
  other v1: -1922.72,4386.53 -2545,4672 -5038.01,5012.34 -4988.11,5014.75 -5014.01,5034.34 -2048,5168 -1991,5169 -1938,5169 -2162,5263 -2116,5263 -2292,5265 -2375,5266 -2047,5358 -1938,5358 -1989,5359
MRFCLK1-2_N: B1.11 PLL1.6 R3.2 TP2.1 | length 547.1
  Top Layer - SIG1 w8: PLL1.6@-1454.07,3618.28 -1440.1,3632.24 -1436.08,3632.24 -1419.92,3648.4 -1419.92,3651.01 TP2.1@-1413.02,3657.92 -1409.42,3661.51 cw(c-1401.43,3653.53) -1401.43,3664.82 -1378.49,3687.77 ; -1378.65,3687.98 -1371.51,3695.13 -1371.13,3695.13 -1364.79,3701.47 R3.2@-1364.79,3720.84 ; B1.11@-1056,3958.68 -1075.98,3958.68 ccw(c-1075.98,3948.98) -1082.84,3955.84 -1085.25,3955.84 ccw(c-1085.25,3893.59) -1129.27,3937.61 -1323.15,3743.73 -1331.27,3735.61 ccw(c-1330.2,3734.54) -1331.71,3734.54 cw(c-1336.45,3739.28) -1336.45,3732.58 ccw(c-1336.45,3692.51) R3.2@-1364.79,3720.84 ; R3.2@-1364.79,3720.84 ccw(c-1336.45,3692.51) -1364.91,3720.72 R3.2@-1364.79,3720.84
MRFCLK1-2_P: B1.12 PLL1.5 R4.2 TP1.1 | length 535.8
  Top Layer - SIG1 w8: PLL1.5@-1440.15,3604.36 -1426.18,3618.32 -1426.18,3622.34 -1410.95,3637.57 -1406.49,3637.57 TP1.1@-1399.58,3644.48 -1394.36,3649.7 ccw(c-1398.45,3653.78) -1392.67,3653.78 -1368.59,3677.87 -1361.23,3685.23 -1354.89,3691.57 R4.2@-1335.51,3691.57 ccw(c-1363.85,3719.9) -1323.78,3719.9 cw(c-1317.07,3719.9) -1321.81,3724.64 -1313.69,3732.76 ccw(c-1314.76,3733.83) -1313.25,3733.83 -1119.37,3927.71 cw(c-1085.25,3893.59) -1085.25,3941.84 -1082.84,3941.84 ccw(c-1075.98,3948.7) -1075.98,3939 B1.12@-1056,3939
MRFCLK2_N: B1.9 FO1.6 | length 3352.3
  Top Layer - SIG1 w8: FO1.6@-4355,3852.78 -4333.58,3874.2 cw(c-4313.08,3853.7) -4313.08,3882.69 -4307.44,3882.69 ccw(c-4307.44,3912.46) -4286.39,3891.41 -4211.88,3965.92 cw(c-4141.17,3895.21) -4141.17,3995.21 -1082.84,3995.21 -1080,3998.06 B1.9@-1056,3998.06
MRFCLK2_P: B1.10 FO1.3 | length 3340.2
  Top Layer - SIG1 w8: FO1.3@-4313.24,3811.02 -4293.6,3830.66 ccw(c-4319.01,3856.06) -4283.08,3856.06 cw(c-4238.68,3856.06) -4270.08,3887.46 ; -4270.31,3887.69 -4264,3894 -4210.18,3947.82 cw(c-4129.57,3867.21) -4129.57,3981.21 -1082.84,3981.21 -1080,3978.37 B1.10@-1056,3978.37
Net*_3: *.3 PLL1.19 R6.1 | length 6854.6
  Top Layer - SIG1 w6: *.3@-6491,6619.61 *.3@-6485.26,6625.34
  Top Layer - SIG1 w8: PLL1.19@-1454.07,3441.5 v1@-1432.51,3419.95
  Bottom Layer - SIG2 w6: *.3@-6485.12,6595.35 -6314.45,6424.68 -4906.49,6424.68 -4845.88,6485.29 -4317.88,6485.29 -4112.07,6279.48 -4112.07,5852.07 -2519,4259 -2099,4259 -1415,3575 -1415,3437.08 v1(-1432.51,3419.57)
  Bottom Layer - SIG2 w8: R6.1@-1411.58,3398.63 ccw(c-1409.88,3400.34) R6.1@-1409.88,3397.93
  Bottom Layer - SIG2 w20: v1(-1432.51,3419.57) R6.1@-1411.58,3398.64
Net*_5: *.5 PLL1.12 R7.2 | length 6308.3
  Top Layer - SIG1 w6: *.5@-6595,6606.5 -6595,6615.61 *.5@-6585.26,6625.34
  Top Layer - SIG1 w8: v1@-1582.13,3569.57 PLL1.12@-1561.25,3548.68
  Bottom Layer - SIG2 w6: *.5@-6585.12,6595.35 -5098.57,5108.81 -3502.81,5108.81 -2568,4174 -2187.09,4174 R7.2@-1647.12,3634.03
  Bottom Layer - SIG2 w8: R7.2@-1647.12,3634.03 -1582.66,3569.57 v1(-1582.51,3569.57)
Net*_7: *.7 BB4.7 | length 1953.8
  Top Layer - SIG1 w6: *.7@-6685.12,6595.35 -6685.12,6520.5 -6342.62,6178 BB4.7@-4948,6178
Net*_8: *.8 BB4.6 | length 1962.4
  Top Layer - SIG1 w6: *.8@-6685.12,6695.35 -6634.62,6644.85 -6634.62,6556.11 -6355.51,6277 BB4.6@-4948,6277
Net*_10: *.10 BB4.8 | length 2186.7
  Top Layer - SIG1 w6: *.10@-6785.12,6695.35 -6732.94,6643.17 -6732.94,6482.97 -6327.97,6078 BB4.8@-4948,6078
Net*_12: *.12 BB4.9 | length 2325.2
  Top Layer - SIG1 w6: *.12@-6885.12,6695.35 -6834.78,6645.01 -6834.78,6489.78 -6323,5978 BB4.9@-4948,5978
Net*_19: *.19 U6.13 | length 6267.1
  Top Layer - SIG1 w6: *.19@-7290,6618.08 -7284,6624.08 *.19@-7285.26,6625.34
  Bottom Layer - SIG2 w6: *.19@-7274.72,6595.35 -7232.64,6637.43 -7232.64,6736.11 -7206.62,6762.13 -1751.71,6762.13 -1424.09,6434.51 -1319.86,6434.51 U6.13@-1299.37,6455
  Bottom Layer - SIG2 w8: *.19@-7285.12,6595.35 *.19@-7274.72,6595.35
Net*_21: *.21 PLL1.8 R125.2 | length 8705.9
  Top Layer - SIG1 w6: *.21@-7385.26,6625.34 -7383,6623.08 -7387,6619.08 *.21@-7382,6614.08 ; -6728.07,5830 -7385.12,6487.05 *.21@-7385.12,6595.35 -7332.78,6647.7 -7332.78,6731.18 -7291.15,6772.8 -5695.42,6772.8 -5433.61,6510.99 -4360.19,6510.99 -4112.07,6262.87 -4112.07,5782.29 v3(-3487.91,5158.13)
  Top Layer - SIG1 w8: v1@-1528.51,3627.3 PLL1.8@-1505.57,3604.36
  Bottom Layer - SIG2 w6: *.21@-7385.26,6570.26 *.21@-7385.26,6625.34 ; v3(-3487.91,5158.13) -3475.76,5158.13 -2537.63,4220 -2123.64,4220 R125.2@-1560.4,3656.76
  Bottom Layer - SIG2 w8: R125.2@-1560.4,3656.76 -1533.11,3629.47 ccw(c-1528.51,3634.07) v1(-1528.51,3627.57) cw(c-1528.51,3629.98) v1@-1530.22,3628.27
Net*_23: *.23 U6.14 | length 6675.9
  Top Layer - SIG1 w6: *.23@-7495,6597.08 *.23@-7491,6601.08 ; *.23@-7485.12,6595.35 *.23@-7485.12,6606.96 ; v3(-5519.76,6740.34) -5570.53,6791.11 -7368.89,6791.11 -7434,6726 -7434,6658.08 *.23@-7485.12,6606.96 ; *.23@-7491,6601.08 *.23@-7485.12,6606.96 ; *.23@-7491,6601.08 -7491,6619.61 -7485.26,6625.34 -7476,6616.08 *.23@-7485.12,6606.96
  Bottom Layer - SIG2 w6: *.23@-7491,6619.61 cw(c-7485.26,6619.61) *.23@-7485.26,6625.34 ; v3(-5519.76,6740.34) -2056.34,6740.34 -1704,6388 -1247.37,6388 U6.14@-1199.37,6436
Net*_24: *.24 U6.17 | length 6290.3
  Bottom Layer - SIG2 w8: *.24@-7485.12,6695.35 -7388.86,6791.61 -1636.37,6791.61 -1481.16,6636.4 -1299.37,6636.4 U6.17@-1299.37,6636
Net*_26: *.26 J10.1 R107.1 | length 3311
  Top Layer - SIG1 w6: *.26@-7585.26,6725.34 -7585.26,6745.42 -7517.79,6812.88 -5009.22,6812.88 -4790.99,6594.66 R107.1@-4715.48,6594.66 ; R107.1@-4713.68,6594.65 J10.1@-4410.9,6592.52
Net*_27: *.27 BB5.2 | length 3234.4
  Top Layer - SIG1 w6: *.27@-7685.12,6595.35 -7685.12,6535.12 -6630,5480 BB5.2@-4948,5480
Net*_28: *.28 BB5.4 | length 3204
  Top Layer - SIG1 w6: *.28@-7685.12,6695.35 -7633.77,6644 -7549,6644 -7534,6629 -7534,6550 -6664,5680 BB5.4@-4948,5680
Net*_29: *.29 R118.2 | length 6224
  Top Layer - SIG1 w6: *.29@-7779,6619.08 -7785.26,6625.34 -7785.26,6463.26 -6458.33,5136.33 -2528.43,5136.33 R118.2@-2354.06,4961.95
Net*_31: *.31 U6.16 | length 7014.4
  Top Layer - SIG1 w6: *.31@-7885.26,6625.34 -7879.5,6619.58 *.31@-7885,6614.07
  Bottom Layer - SIG2 w6: *.31@-7885.67,6595.9 -7835,6646.57 -7835,6769 -7794.08,6809.92 -4828.43,6809.92 -4828.32,6809.81 -1460.36,6809.81 -1336.92,6686.37 -1284.37,6686.37 -1249.05,6651.06 -1249.05,6585.68 U6.16@-1199.37,6536
Net*_32: *.32 BB5.3 | length 3497.2
  Top Layer - SIG1 w6: *.32@-7885.12,6695.35 -7832.47,6748 -7766,6748 -7734,6716 -7734,6671 -7706,6643 -7660.97,6643 -7633,6615.03 -7633,6567 -6646,5580 BB5.3@-4948,5580
Net*_33: *.33 BB5.1 | length 3648.7
  Top Layer - SIG1 w6: *.33@-7985.12,6595.35 -7978.65,6595.35 -7928.65,6645.35 -7756.35,6645.35 -7732.31,6621.31 -7732.31,6507.31 -6605,5380 BB5.1@-4948,5380
Net*_35: *.35 BB11.4 | length 1328.3
  Top Layer - SIG1 w8: *.35@-8085.12,6595.35 -7899.1,6409.34 BB11.4@-7899.1,5344.11
Net*_36: *.36 R119.1 | length 716.2
  Top Layer - SIG1 w6: *.36@-8085.26,6725.34 -8085.26,6693.64 -8136,6642.9 -8136,6543 -7932.5,6339.5 v3(-7932.5,6154.5)
  Bottom Layer - SIG2 w8: v3(-7932.5,6154.5) -7932.5,6114.96 R119.1@-7932.17,6114.63
Net*_37: *.37 BB11.3 | length 1328.3
  Top Layer - SIG1 w8: *.37@-8185.12,6595.35 -8185.12,6492.59 -7999.1,6306.58 BB11.3@-7999.1,5344.11
Net*_38: *.38 U6.4 | length 8052.2
  Top Layer - SIG1 w6: *.38@-8185.26,6725.34 -8185.26,6745.42 -8104.15,6826.53 -1159.18,6826.53 -1080.44,6747.79 -1080.44,6054.93 U6.4@-1199.37,5936
Net*_40: *.40 BB11.2 | length 1428.3
  Top Layer - SIG1 w8: *.40@-8285.12,6695.35 -8237.82,6648.05 -8237.82,6426.31 -8099.1,6287.6 BB11.2@-8099.1,5344.11
NetAUX1_1: AUX1.1 J14.1 R119.2 R120.2 | length 6266.4
  Top Layer - SIG1 w6: -4836.6,1973.1 -4836.6,1353.31 -4747.35,1264.06 AUX1.1@-4690.6,1264.06
  Top Layer - SIG1 w8: J14.1@-5177.3,2262.28 -5125.78,2262.28 -4836.6,1973.1
  Bottom Layer - SIG2 w6: R119.2@-7894.38,6114.63 -7852.26,6114.63 R120.2@-7851.9,6115 -7851.9,5800.64 -5632.41,3581.15 -5632.41,2717.39 J14.1@-5177.3,2262.28
NetB1_1: B1.1 C19.2 D1.3 | length 434.6
  Top Layer - SIG1 w8: B1.1@-926,3939 -890.77,3939 ccw(c-890.77,3941.77) -888,3941.77 ; D1.3@-632.69,3939 ccw(c-632.69,3948.46) D1.3@-626,3941.77 -628.77,3939 D1.3@-632.69,3939
  Top Layer - SIG1 w18: -888,3939 D1.3@-626,3939 ; D1.3@-625.04,3940.81 C19.2@-508.64,3940.81
  Top Layer - SIG1 w20: D1.3@-626,3941.77 D1.3@-625.04,3940.81
NetB1_2: B1.2 B1.16 C20.2 | length 273.1
  Top Layer - SIG1 w8: B1.16@-961.47,3888.46 B1.16@-961.47,3903.53 ; B1.2@-926,3958.68 -900.35,3958.68 ccw(c-900.35,3988.04) v1(-871,3988.04) ; v1(-871,3900) -955.59,3900 B1.16@-959.81,3904.22 ; B1.16@-961.47,3903.53 cw(c-959.81,3901.86) B1.16@-959.81,3904.22 ; B1.16@-961.47,3903.53 cw(c-959.81,3901.86) B1.16@-959.81,3904.22 ; B1.16@-961.47,3903.53 cw(c-959.81,3901.86) B1.16@-959.81,3904.22
  Bottom Layer - SIG2 w8: v1(-871,3900) -871,3937.08 ccw(c-873.72,3937.08) C20.2@-871.8,3939 -871,3938.2 v1(-871,3988.04)
NetB3_1: B3.1 C83.2 | length 69.8
  Top Layer - SIG1 w8: B3.1@-2891.12,1146.51 B3.1@-2882.76,1146.51 ; B3.1@-2890.17,1145.99 cw(c-2890.17,1147.33) B3.1@-2891.12,1146.38 -2831.64,1146.38 C83.2@-2831.02,1147
NetB3_2: B3.2 B3.16 C84.2 | length 332.2
  Top Layer - SIG1 w8: B3.16@-2926.59,1110.91 -2873.58,1110.91 -2847.84,1085.16 v3(-2847.84,1084.16) ; B3.2@-2891.12,1166.06 -2867.06,1166.06 v1(-2847.12,1186) -2846.08,1187.04 C84.2@-2811.39,1187.04
  Bottom Layer - SIG2 w8: -2891.12,1166.06 -2867.06,1166.06 v1@-2847.84,1185.29 ; v3(-2847.84,1084.16) v1@-2847.84,1185.29 ; v1(-2847.12,1186) v1@-2847.84,1185.29
NetB3_11: B3.11 R90.1 R93.2 | length 137
  Top Layer - SIG1 w6: R93.2@-3075.07,1115.9 R93.2@-3074.97,1116
  Top Layer - SIG1 w8: R93.2@-3075.07,1115.9 -3075.07,1146.61 -3055.62,1166.06 B3.11@-3021.12,1166.06
  Bottom Layer - SIG2 w8: R90.1@-3075.51,1115.58 -3075.51,1149.01 v1(-3067.92,1156.59)
NetB3_12: B3.12 R89.1 R92.2 | length 178.9
  Top Layer - SIG1 w8: -3023.59,1140.41 cw(c-3015.15,1140.41) B3.12@-3021.12,1146.38 -3024.35,1143.15 v1(-3024.35,1064.4) -3024.35,1021.93 -3022.94,1020.52 R89.1@-3022.94,976.03
NetB4_5: B4.5 B5.6 | length 450
  Top Layer - SIG1 w6: B5.6@-1685.69,4897.75 -1685.26,4898.18 -1638.66,4898.18 -1583.82,4898.18 -1504.56,4977.44 B4.5@-1268.74,4977.44
NetB5_1: B5.1 B5.3 R110.1 R113.1 U7.4 | length 1255.8
  Top Layer - SIG1 w6: R113.1@-2664.36,4672 R110.1@-2620.9,4672 ; R110.1@-2624.9,4672 -2586.9,4634 -2512,4634 -2436.22,4558.22 U7.4@-2436.22,4523.74 ; B5.3@-1772.31,4846.57 -1830.75,4846.57 cw(c-1830.75,4933.82) v1(-1892.44,4872.12) cw(c-1830.58,4810.25) -1830.58,4897.75 B5.1@-1772.31,4897.75
  Bottom Layer - SIG2 w6: U7.4@-2436.22,4523.74 -2201.96,4758 -2120,4758 -2005.88,4872.12 v1(-1892.44,4872.12)
NetB5_4: B5.4 B6.5 | length 482.5
  Top Layer - SIG1 w8: B5.4@-1685.69,4846.57 -1592.57,4846.57 v3(-1512,4766)
  Bottom Layer - SIG2 w8: v3(-1512,4766) -1432.82,4686.82 B6.5@-1269.37,4686.82
NetB7_5: B7.5 B8.6 | length 491.6
  Bottom Layer - SIG2 w6: B8.6@-1686.21,4700.16 B8.6@-1685.78,4700.59 ; B8.6@-1684.62,4701.75 B8.6@-1685.78,4700.59 ; B7.5@-1268.74,4875.08 -1451.92,4875.08 -1613.8,4713.2 -1626.41,4700.59 B8.6@-1685.78,4700.59
NetB8_1: B8.1 B8.3 R111.1 R114.1 U7.6 | length 1196.8
  Top Layer - SIG1 w6: R114.1@-2621.31,4806.74 R111.1@-2580.74,4806.74 ; R111.1@-2581.53,4797.16 -2581.53,4788.53 -2357.48,4564.48 U7.6@-2357.48,4523.74 ; R111.1@-2581.19,4808.08 ccw(c-2579.66,4808.08) R111.1@-2580.74,4807
  Bottom Layer - SIG2 w6: U7.6@-2357.48,4523.74 -2157.02,4724.2 -1862.55,4724.2 ; B8.1@-1772.83,4700.16 -1804.51,4700.16 cw(c-1804.51,4782.23) -1862.55,4724.2 ; B8.3@-1755.11,4751.34 B8.3@-1772.83,4751.34 -1797.03,4751.34 ccw(c-1797.03,4658.67) -1862.55,4724.2
NetB8_4: B8.4 B9.5 | length 634.3
  Bottom Layer - SIG2 w6: B8.4@-1686.21,4751.34 -1713.61,4751.34 -1727,4737.95 -1727,4673 -1702,4648 -1570,4648 -1429.82,4507.82 B9.5@-1272.37,4507.82
NetB10_5: B10.5 B11.6 | length 446.8
  Bottom Layer - SIG2 w6: B11.6@-1683.21,4401.16 -1682.78,4401.59 -1589.59,4401.59 -1511.63,4323.63 B10.5@-1273.77,4323.63 cw(c-1278.16,4328.02) B10.5@-1278.16,4321.81
NetB11_1: B11.1 R112.1 R116.1 U7.10 | length 828.4
  Top Layer - SIG1 w6: R116.1@-2309.6,4728.14 R116.1@-2311.5,4730.03 ; R112.1@-2274.31,4730.31 -2273,4729 cw(c-2273,4732.53) -2275.5,4730.03 R116.1@-2311.5,4730.03 ; R112.1@-2269.39,4730.14 -2269.5,4730.03 -2200,4660.54 U7.10@-2200,4523.74 ; R116.1@-2311.5,4730.03 R116.1@-2311.6,4730.14 -2311.6,4730.03 R116.1@-2311.5,4730.03
  Bottom Layer - SIG2 w6: U7.10@-2200,4523.74 -2121.74,4602 -2015.3,4602 -1814.45,4401.16 B11.1@-1769.83,4401.16 cw(c-1773.23,4404.56) B11.1@-1773.23,4399.75
NetB11_3: B11.3 B13.5 M1.1 | length 601.6
  Top Layer - SIG1 w6: v3(-1724,4506.15) -1724,4512.31 M1.1@-1684.37,4551.94 ; M1.1@-1696.28,4551.94 M1.1@-1684.37,4551.94 ; B13.5@-1277.8,4430.02 B13.5@-1273.77,4425.99 -1501.99,4425.99 -1627.94,4551.94 M1.1@-1684.37,4551.94
  Bottom Layer - SIG2 w6: B11.3@-1763.83,4456.28 v3@-1722.06,4498.06
NetB11_4: B11.4 B12.5 | length 476.2
  Top Layer - SIG1 w6: v3(-1516.99,4525.01) -1431.82,4610.18 B12.5@-1272.37,4610.18
  Bottom Layer - SIG2 w6: B11.4@-1683.21,4452.34 -1682.78,4452.77 -1589.23,4452.77 v3(-1516.99,4525.01)
NetB14_5: B14.5 M1.3 | length 492.1
  Top Layer - SIG1 w6: M1.3@-1684.37,4603.12 -1683.94,4603.55 -1611.45,4603.55 -1425.82,4789.18 B14.5@-1269.37,4789.18
NetBC1_7: BC1.7 R63.1 | length 122
  Top Layer - SIG1 w8: BC1.7@-4028.6,2777.76 -3976.09,2725.25 v1(-3975.29,2725.25)
  Bottom Layer - SIG2 w8: R63.1@-4008.91,2757.42 -4007.46,2757.42 v1(-3975.29,2725.25)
